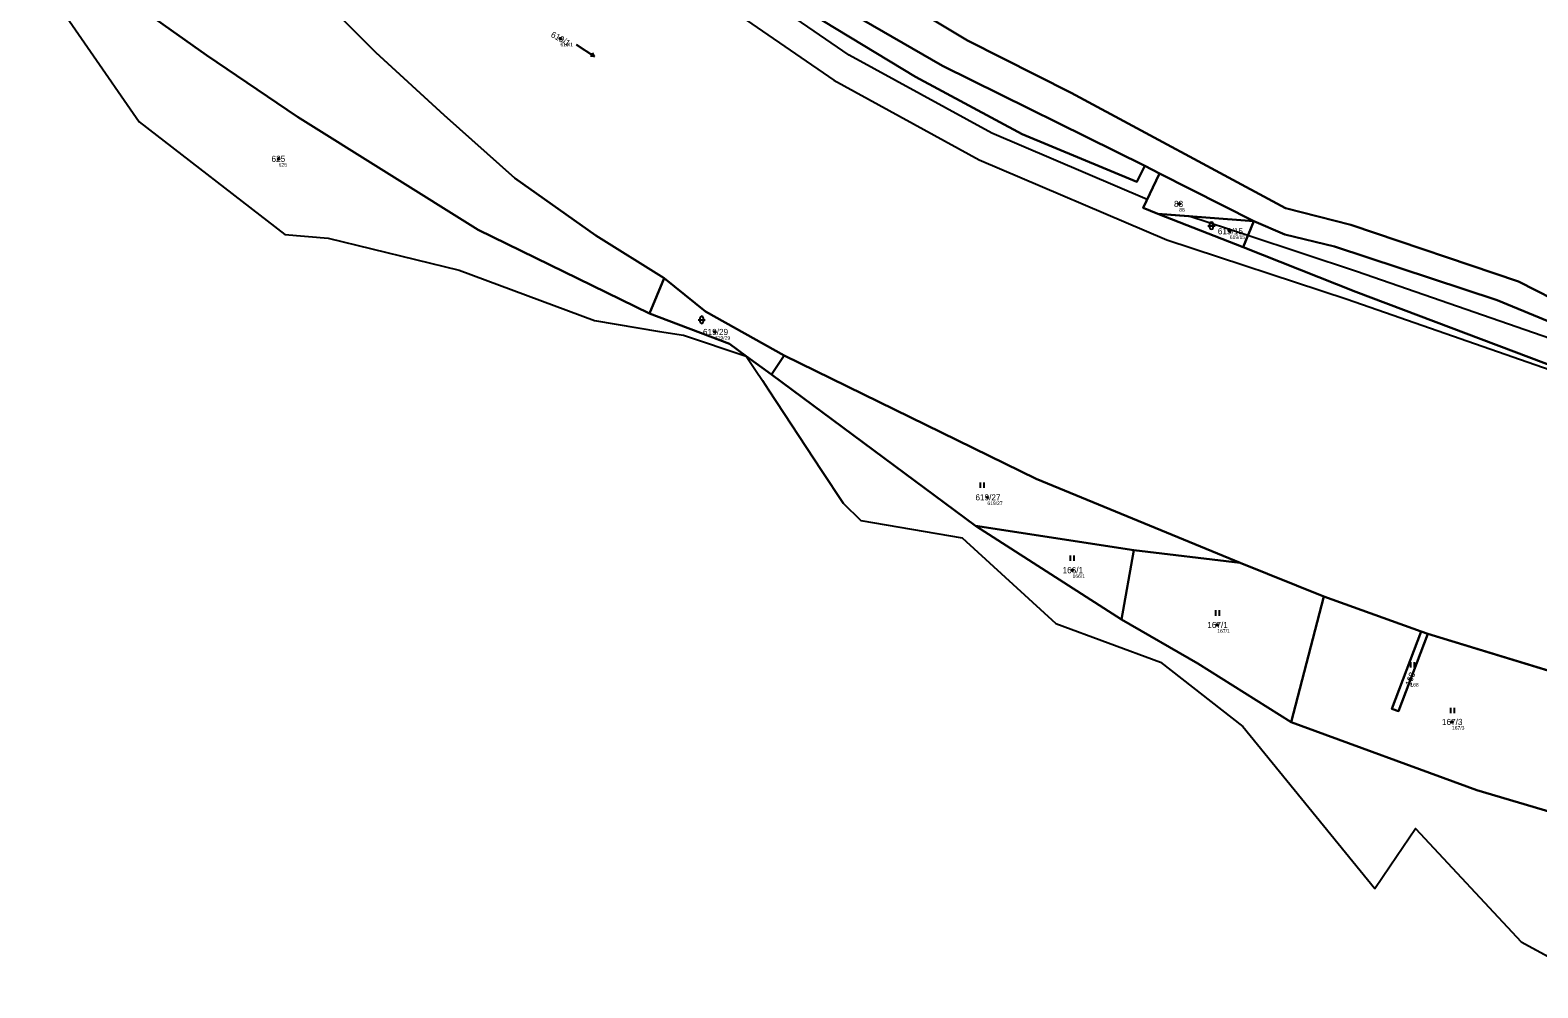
# Model space of a CAD drawing. Extents: x -766177 to -763254, y -1057727 to -1053915.
# Drawn here: x -765543.3 to -765125.5, y -1057694.1 to -1057428.8 of the extents above; entities that cross this region are included whole.
import ezdxf

# ---------------------------------------------------------------- set-up
doc = ezdxf.new("R2010")
doc.units = 0
for name, color, linetype in [('Vrstva 1', 7, 'Continuous'), ('Vrstva 13', 7, 'Continuous'), ('Vrstva 2', 7, 'Continuous'), ('Vrstva 3', 7, 'Continuous'), ('Vrstva 50', 7, 'Continuous'), ('Vrstva 51', 7, 'Continuous'), ('Vrstva 53', 7, 'Continuous')]:
    doc.layers.add(name, color=color, linetype=linetype)

msp = doc.modelspace()

# ---------------------------------------------------------------- linework, layer by layer
at = {"layer": 'Vrstva 1'}
for p, q in [((-765234.41, -1057466.37), (-765230.36, -1057468.47)), ((-765204.25, -1057481.71), (-765230.36, -1057468.47)), ((-765207.18, -1057488.95), (-765230.8, -1057479.63)), ((-765230.8, -1057479.63), (-765204.25, -1057481.71)), ((-765204.25, -1057481.71), (-765207.18, -1057488.95)), ((-765472.78, -1057485.44), (-765460.74, -1057486.38)), ((-765367.63, -1057497.49), (-765371.71, -1057507.33)), ((-765386.9, -1057509.23), (-765368.96, -1057512.29)), ((-765344.88, -1057519.09), (-765337.93, -1057524.15)), ((-765334.4, -1057518.93), (-765337.93, -1057524.15)), ((-765337.93, -1057524.15), (-765281.36, -1057566.09)), ((-765338.73, -1057528.42), (-765324, -1057550.76)), ((-765281.36, -1057566.09), (-765240.93, -1057592.09)), ((-765237.48, -1057572.84), (-765281.36, -1057566.09)), ((-765240.93, -1057592.09), (-765237.48, -1057572.84)), ((-765207.99, -1057576.4), (-765237.48, -1057572.84)), ((-765184.8, -1057585.68), (-765207.99, -1057576.4)), ((-765193.89, -1057620.48), (-765184.8, -1057585.68)), ((-765157.84, -1057595.42), (-765184.8, -1057585.68)), ((-765156.02, -1057596.08), (-765157.84, -1057595.42)), ((-765110.38, -1057609.97), (-765156.02, -1057596.08)), ((-765166.41, -1057660.33), (-765159.4, -1057649.95)), ((-765159.4, -1057649.95), (-765130.14, -1057681.4)), ((-765170.7, -1057666.65), (-765166.41, -1057660.33)), ((-765130.14, -1057681.4), (-765106.64, -1057694.14))]:
    msp.add_line(p, q, dxfattribs=at)
for points in [[(-765394.04, -1057071.91), (-765403.63, -1057105.4), (-765412.86, -1057132.02), (-765419.76, -1057147.24), (-765423.75, -1057154.72), (-765441.83, -1057183.07), (-765453.75, -1057219.22), (-765455.05, -1057226.3), (-765455.77, -1057234.84), (-765454.13, -1057242.93), (-765443.82, -1057279.53), (-765438.49, -1057294.54), (-765415.84, -1057325.94), (-765407.31, -1057335.4), (-765349.8, -1057387.03), (-765324, -1057406.99), (-765309.93, -1057415.78), (-765283.58, -1057431.65), (-765254.84, -1057446.17), (-765195.48, -1057478.07), (-765177.36, -1057482.72), (-765130.89, -1057498.41), (-765116.39, -1057505.83)], [(-765524.06, -1057334.33), (-765515.84, -1057347.07), (-765490.68, -1057385.84), (-765476.84, -1057403.38), (-765460.05, -1057422.54), (-765447.54, -1057434.98), (-765428.56, -1057452.31), (-765409.04, -1057469.75), (-765386.59, -1057485.65), (-765367.63, -1057497.49)], [(-765424.12, -1057332.79), (-765395.35, -1057365.63), (-765372.51, -1057389.53), (-765353.63, -1057406.44), (-765334.45, -1057419.55), (-765297.97, -1057441.74), (-765268.43, -1057457.6), (-765236.67, -1057470.81), (-765234.41, -1057466.37)], [(-765234.41, -1057466.37), (-765290.46, -1057438.69), (-765315.38, -1057424.3), (-765338.88, -1057408.59), (-765350.6, -1057398.98), (-765410.39, -1057345.3), (-765423.28, -1057332.01)], [(-765556.15, -1057391.99), (-765513.15, -1057454.19), (-765472.78, -1057485.44)], [(-765371.71, -1057507.33), (-765419.19, -1057484.11), (-765469.25, -1057452.77), (-765494.47, -1057435.72), (-765556.15, -1057391.99)], [(-765230.36, -1057468.47), (-765234.93, -1057478), (-765230.8, -1057479.63)], [(-765204.25, -1057481.71), (-765195.64, -1057485.42), (-765181.88, -1057488.75), (-765136.83, -1057503.56), (-765106.6, -1057516.04), (-764983.41, -1057548.37), (-764976.12, -1057552.21)], [(-765460.74, -1057486.38), (-765424.45, -1057495.29), (-765386.9, -1057509.23)], [(-764976.89, -1057558.49), (-764998.98, -1057554.31), (-765097.42, -1057530.92), (-765175.94, -1057501.28), (-765207.18, -1057488.95)], [(-765367.63, -1057497.49), (-765356.18, -1057506.7), (-765334.4, -1057518.93)], [(-765371.71, -1057507.33), (-765349.57, -1057515.67), (-765344.88, -1057519.09)], [(-765368.96, -1057512.29), (-765362.32, -1057513.26), (-765344.88, -1057519.09)], [(-765344.88, -1057519.09), (-765342.32, -1057522.98), (-765340.41, -1057525.86), (-765339.54, -1057527.11), (-765338.73, -1057528.42)], [(-765334.4, -1057518.93), (-765264.51, -1057553.11), (-765207.99, -1057576.4)], [(-765324, -1057550.76), (-765318, -1057559.86), (-765313.14, -1057564.63)], [(-765313.14, -1057564.63), (-765285.04, -1057569.46), (-765259.08, -1057593.22), (-765230.13, -1057603.92), (-765207.27, -1057621.74), (-765170.7, -1057666.65)], [(-765240.93, -1057592.09), (-765219.73, -1057604.26), (-765193.89, -1057620.48)], [(-765156.02, -1057596.08), (-765164.11, -1057617.49), (-765165.94, -1057616.83), (-765157.84, -1057595.42)], [(-765193.89, -1057620.48), (-765142.39, -1057639.37), (-765119.35, -1057646.23)]]:
    msp.add_lwpolyline(points, dxfattribs=at)
at = {"layer": 'Vrstva 13'}
for points in [[(-765512.12, -1057082.89), (-765501.32, -1057139.68), (-765504.26, -1057140.28), (-765491.86, -1057200.73), (-765481.38, -1057240.77), (-765461.06, -1057288.95), (-765449.51, -1057310.88), (-765418.19, -1057356.19), (-765379.68, -1057397.95), (-765352.48, -1057420.78), (-765320.63, -1057442.66), (-765280.38, -1057464.71), (-765228.33, -1057486.89), (-765178.4, -1057503.35), (-765101.09, -1057530.16)], [(-765098.76, -1057522.33), (-765175.79, -1057495.62), (-765205.87, -1057485.71), (-765207.18, -1057488.95), (-765230.8, -1057479.63), (-765234.93, -1057478), (-765233.82, -1057475.68), (-765276.81, -1057457.36), (-765316.35, -1057435.71), (-765347.54, -1057414.28)]]:
    msp.add_lwpolyline(points, dxfattribs=at)
msp.add_lwpolyline([(-765222.27, -1057480.3), (-765230.8, -1057479.63), (-765207.18, -1057488.95), (-765205.87, -1057485.71)], close=True, dxfattribs=at)
at = {"layer": 'Vrstva 3'}
for p, q in [((-765392.006, -1057432.783), (-765386.974, -1057436.05)), ((-765386.974, -1057436.05), (-765388.067, -1057435.939)), ((-765386.974, -1057436.05), (-765387.521, -1057435.098)), ((-765216.981, -1057482.961), (-765214.979, -1057482.961)), ((-765216.481, -1057482.461), (-765216.481, -1057483.462)), ((-765215.479, -1057483.462), (-765215.479, -1057482.461)), ((-765358.251, -1057509.041), (-765356.249, -1057509.041)), ((-765357.751, -1057508.541), (-765357.751, -1057509.542)), ((-765356.749, -1057509.542), (-765356.749, -1057508.541)), ((-765279.941, -1057555.61), (-765279.941, -1057554.11)), ((-765278.94, -1057555.61), (-765278.94, -1057554.11)), ((-765255.051, -1057575.84), (-765255.051, -1057574.34)), ((-765254.05, -1057575.84), (-765254.05, -1057574.34)), ((-765214.781, -1057591.02), (-765214.781, -1057589.52)), ((-765213.78, -1057591.02), (-765213.78, -1057589.52)), ((-765160.701, -1057605.39), (-765160.701, -1057603.89)), ((-765159.7, -1057605.39), (-765159.7, -1057603.89)), ((-765149.611, -1057618.02), (-765149.611, -1057616.52)), ((-765148.61, -1057618.02), (-765148.61, -1057616.52))]:
    msp.add_line(p, q, dxfattribs=at)
for centre, start, end in [((-765215.98, -1057482.4609), 0, 180), ((-765215.98, -1057483.4609), 180, 359.9878861), ((-765357.25, -1057508.5409), 0, 180), ((-765357.25, -1057509.5409), 180, 359.9878861)]:
    msp.add_arc(centre, 0.5, start, end, dxfattribs=at)
at = {"layer": 'Vrstva 50'}
for centre in [(-765396.37, -1057431.10994), (-765474.47, -1057464.42994), (-765224.9, -1057476.91994), (-765210.89, -1057484.48994), (-765353.57, -1057512.39994), (-765278.07, -1057558.21994), (-765254.46, -1057578.40994), (-765214.35, -1057593.58994), (-765160.85, -1057608.48994), (-765149.31, -1057620.45994)]:
    msp.add_circle(centre, 0.25, dxfattribs=at)
at = {"layer": 'Vrstva 51'}
for points in [[(-765116.39, -1057505.83), (-765130.89, -1057498.41), (-765177.36, -1057482.72), (-765195.48, -1057478.07), (-765254.84, -1057446.17), (-765283.58, -1057431.65), (-765309.93, -1057415.78), (-765324, -1057406.99), (-765349.8, -1057387.03), (-765407.31, -1057335.4), (-765415.84, -1057325.94), (-765438.49, -1057294.54), (-765443.82, -1057279.53), (-765454.13, -1057242.93), (-765455.77, -1057234.84), (-765455.05, -1057226.3), (-765453.75, -1057219.22), (-765441.83, -1057183.07), (-765423.75, -1057154.72), (-765419.76, -1057147.24), (-765412.86, -1057132.02), (-765403.63, -1057105.4), (-765394.04, -1057071.91)], [(-765394.04, -1057071.91), (-765403.63, -1057105.4), (-765412.86, -1057132.02), (-765419.76, -1057147.24), (-765423.75, -1057154.72), (-765441.83, -1057183.07), (-765453.75, -1057219.22), (-765455.05, -1057226.3), (-765455.77, -1057234.84), (-765454.13, -1057242.93), (-765443.82, -1057279.53), (-765438.49, -1057294.54), (-765415.84, -1057325.94), (-765407.31, -1057335.4), (-765349.8, -1057387.03), (-765324, -1057406.99), (-765309.93, -1057415.78), (-765283.58, -1057431.65), (-765254.84, -1057446.17), (-765195.48, -1057478.07), (-765177.36, -1057482.72), (-765130.89, -1057498.41), (-765116.39, -1057505.83)], [(-765545.44, -1057285.45), (-765531.12, -1057317.29), (-765524.06, -1057334.33), (-765515.84, -1057347.07), (-765490.68, -1057385.84), (-765476.84, -1057403.38), (-765460.05, -1057422.54), (-765447.54, -1057434.98), (-765428.56, -1057452.31), (-765409.04, -1057469.75), (-765386.59, -1057485.65), (-765367.63, -1057497.49), (-765356.18, -1057506.7), (-765334.4, -1057518.93), (-765264.51, -1057553.11)], [(-765556.15, -1057391.99), (-765494.47, -1057435.72), (-765469.25, -1057452.77), (-765419.19, -1057484.11), (-765371.71, -1057507.33), (-765367.63, -1057497.49), (-765386.59, -1057485.65), (-765409.04, -1057469.75), (-765428.56, -1057452.31), (-765447.54, -1057434.98), (-765460.05, -1057422.54), (-765476.84, -1057403.38), (-765490.68, -1057385.84), (-765515.84, -1057347.07), (-765524.06, -1057334.33), (-765529.78, -1057331.58), (-765537.31, -1057328.77), (-765544.25, -1057327.28)], [(-765097.42, -1057530.92), (-765175.94, -1057501.28), (-765207.18, -1057488.95), (-765230.8, -1057479.63), (-765234.93, -1057478), (-765230.36, -1057468.47), (-765234.41, -1057466.37), (-765236.67, -1057470.81), (-765268.43, -1057457.6), (-765297.97, -1057441.74), (-765334.45, -1057419.55)], [(-765315.38, -1057424.3), (-765290.46, -1057438.69), (-765234.41, -1057466.37), (-765230.36, -1057468.47), (-765204.25, -1057481.71), (-765195.64, -1057485.42), (-765181.88, -1057488.75), (-765136.83, -1057503.56), (-765106.6, -1057516.04)], [(-765119.35, -1057646.23), (-765142.39, -1057639.37), (-765193.89, -1057620.48), (-765219.73, -1057604.26), (-765240.93, -1057592.09), (-765281.36, -1057566.09), (-765337.93, -1057524.15), (-765344.88, -1057519.09), (-765342.32, -1057522.98), (-765340.41, -1057525.86), (-765339.54, -1057527.11), (-765338.73, -1057528.42), (-765324, -1057550.76), (-765318, -1057559.86), (-765313.14, -1057564.63), (-765285.04, -1057569.46), (-765259.08, -1057593.22), (-765230.13, -1057603.92), (-765207.27, -1057621.74), (-765170.7, -1057666.65), (-765166.41, -1057660.33), (-765159.4, -1057649.95), (-765130.14, -1057681.4), (-765106.64, -1057694.14)], [(-765264.51, -1057553.11), (-765207.99, -1057576.4), (-765184.8, -1057585.68), (-765157.84, -1057595.42), (-765156.02, -1057596.08), (-765110.38, -1057609.97)]]:
    msp.add_lwpolyline(points, dxfattribs=at)
for points in [[(-765395.35, -1057365.63), (-765372.51, -1057389.53), (-765353.63, -1057406.44), (-765334.45, -1057419.55), (-765297.97, -1057441.74), (-765268.43, -1057457.6), (-765236.67, -1057470.81), (-765234.41, -1057466.37), (-765290.46, -1057438.69), (-765315.38, -1057424.3), (-765338.88, -1057408.59), (-765350.6, -1057398.98), (-765410.39, -1057345.3), (-765423.28, -1057332.01), (-765424.12, -1057332.79)], [(-765371.71, -1057507.33), (-765419.19, -1057484.11), (-765469.25, -1057452.77), (-765494.47, -1057435.72), (-765556.15, -1057391.99), (-765513.15, -1057454.19), (-765472.78, -1057485.44), (-765460.74, -1057486.38), (-765424.45, -1057495.29), (-765386.9, -1057509.23), (-765368.96, -1057512.29), (-765362.32, -1057513.26), (-765344.88, -1057519.09), (-765349.57, -1057515.67)], [(-765230.8, -1057479.63), (-765204.25, -1057481.71), (-765230.36, -1057468.47), (-765234.93, -1057478)], [(-765204.25, -1057481.71), (-765230.8, -1057479.63), (-765207.18, -1057488.95)], [(-765207.18, -1057488.95), (-765175.94, -1057501.28), (-765097.42, -1057530.92), (-764998.98, -1057554.31), (-764976.89, -1057558.49), (-764976.12, -1057552.21), (-764983.41, -1057548.37), (-765106.6, -1057516.04), (-765136.83, -1057503.56), (-765181.88, -1057488.75), (-765195.64, -1057485.42), (-765204.25, -1057481.71)], [(-765349.57, -1057515.67), (-765344.88, -1057519.09), (-765337.93, -1057524.15), (-765334.4, -1057518.93), (-765356.18, -1057506.7), (-765367.63, -1057497.49), (-765371.71, -1057507.33)], [(-765337.93, -1057524.15), (-765281.36, -1057566.09), (-765237.48, -1057572.84), (-765207.99, -1057576.4), (-765264.51, -1057553.11), (-765334.4, -1057518.93)], [(-765237.48, -1057572.84), (-765281.36, -1057566.09), (-765240.93, -1057592.09)], [(-765193.89, -1057620.48), (-765184.8, -1057585.68), (-765207.99, -1057576.4), (-765237.48, -1057572.84), (-765240.93, -1057592.09), (-765219.73, -1057604.26)], [(-765119.35, -1057646.23), (-765110.38, -1057609.97), (-765156.02, -1057596.08), (-765164.11, -1057617.49), (-765165.94, -1057616.83), (-765157.84, -1057595.42), (-765184.8, -1057585.68), (-765193.89, -1057620.48), (-765142.39, -1057639.37)], [(-765156.02, -1057596.08), (-765157.84, -1057595.42), (-765165.94, -1057616.83), (-765164.11, -1057617.49)]]:
    msp.add_lwpolyline(points, close=True, dxfattribs=at)
at = {"layer": 'Vrstva 53'}
msp.add_lwpolyline([(-765556.15, -1057391.99), (-765513.15, -1057454.19), (-765472.78, -1057485.44), (-765460.74, -1057486.38), (-765424.45, -1057495.29), (-765386.9, -1057509.23), (-765368.96, -1057512.29), (-765362.32, -1057513.26), (-765344.88, -1057519.09), (-765342.32, -1057522.98), (-765340.41, -1057525.86), (-765339.54, -1057527.11), (-765338.73, -1057528.42), (-765324, -1057550.76), (-765318, -1057559.86), (-765313.14, -1057564.63), (-765285.04, -1057569.46), (-765259.08, -1057593.22), (-765230.13, -1057603.92), (-765207.27, -1057621.74), (-765170.7, -1057666.65), (-765166.41, -1057660.33), (-765159.4, -1057649.95), (-765130.14, -1057681.4), (-765106.64, -1057694.14)], dxfattribs=at)

# ---------------------------------------------------------------- texts
at = {"layer": 'Vrstva 2'}
for s, rotation, p in [('619/1', 331, (-765399.207, -1057430.508)), ('168', 70, (-765160.726, -1057610.636))]:
    msp.add_text(s, height=1.699998, rotation=rotation, dxfattribs=at).set_placement(p)
for s, p in [('625', (-765476.444, -1057465.28)), ('88', (-765226.342, -1057477.77)), ('619/15', (-765214.195, -1057485.34)), ('619/29', (-765356.875, -1057513.25)), ('619/27', (-765281.375, -1057559.07)), ('166/1', (-765257.233, -1057579.26)), ('167/1', (-765217.123, -1057594.44)), ('167/3', (-765152.083, -1057621.31))]:
    msp.add_text(s, height=1.699998, dxfattribs=at).set_placement(p)
at = {"layer": 'Vrstva 50'}
for s, p in [('619/1', (-765396.37, -1057433.266)), ('625', (-765474.47, -1057466.586)), ('88', (-765224.9, -1057479.076)), ('619/15', (-765210.89, -1057486.646)), ('619/29', (-765353.57, -1057514.556)), ('619/27', (-765278.07, -1057560.376)), ('166/1', (-765254.46, -1057580.566)), ('167/1', (-765214.35, -1057595.746)), ('168', (-765160.85, -1057610.646)), ('167/3', (-765149.31, -1057622.616))]:
    msp.add_text(s, height=0.999996, dxfattribs=at).set_placement(p)

doc.saveas('drawing.dxf')
